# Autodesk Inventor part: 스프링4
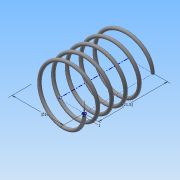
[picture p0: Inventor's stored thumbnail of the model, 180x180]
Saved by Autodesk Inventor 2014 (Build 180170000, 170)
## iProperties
Created: 2015-06
Part Number: 스프링4
Material: 강철, 연강
Document SubType Name: Modeling
Designer: Administrator
Density: 7.86 g/cm^3
Appearance: 강철
Mass: 1.53535 g
Surface Area: 7.89042 cm^2
Volume: 0.195337 cm^3
Author: Administrator
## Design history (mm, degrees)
sketch "스케치1"
  geometry: L1 (0, 0)-(8, 0); L2 (8, 0)-(8, 21.5); L3 (8, 21.5)-(0, 21.5); L4 (0, 21.5)-(0, 0); C1 r 0.5 at (8, 0)
  constraints: 8 end point, 2 parallel, 1 centre point, 1 coincident, 1 horizontal, 1 perpendicular
  dimensions: "d0" = 16 diameter of L2 L4; "d1" = 21.5 distance of L1.end L2.end (derived); "d2" = 1 diameter of C1
feature "코일1" sketch "스케치1" pitch "d3" = 10; turns "d5" = 5; dims "d4" = 21.5 (= d1), "d6" = 0, angle "d7" = 90 deg, angle "d8" = 90 deg, "d9" = 0, "d10" = 0
sketch "스케치2"
  geometry: L1 (-8.5, 0)-(-7.5, 0) reference; 1 further point
  constraints: 1 horizontal alignment
extrude "돌출1" cut sketch "스케치2" stored distance "d11" = 10; taper "d12" = 0 deg
node "작업 평면1"
sketch "스케치3"
  geometry: L1 (8.5, 0)-(7.5, 0) reference; 1 further point
  constraints: 1 horizontal alignment
extrude "돌출2" cut sketch "스케치3" stored distance "d14" = 10; taper "d15" = 0 deg
node "솔리드1"
node "절단 모서리 투영1"
node "절단 모서리 투영2"
other parameters: "d13" = -21.5 (= -d1)
